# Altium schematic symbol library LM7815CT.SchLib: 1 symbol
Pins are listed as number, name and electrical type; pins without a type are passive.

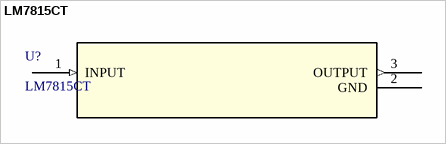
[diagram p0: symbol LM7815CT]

## LM7815CT
designator U?
Description; Manufacturer_Name: Texas Instruments
footprint TO-220_TEX
pins: 1 INPUT (in), 2 GND (power), 3 OUTPUT (out)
